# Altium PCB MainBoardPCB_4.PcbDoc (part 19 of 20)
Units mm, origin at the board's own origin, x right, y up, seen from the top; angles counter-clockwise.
Board outline 333.63 x 349.38 mm, 16 copper layers (L1, L2 (GND), L3 (Sign), L4 (GND), L5 (Sign), L6 (PWR/GND), L7(PWR/GND), L8 (Plane_GND), L9 (PWR/GND), L10 (PWR/GND), L11 (PWR/GND), L12 (Sign), L13 (GND), L14 (Sign), L15 (GND), L16), stack 2.502 mm thick; 2205 components, 1648 nets, 8314 pads, 3172 vias.
Unrouted connection lines stored in the file: 5141.
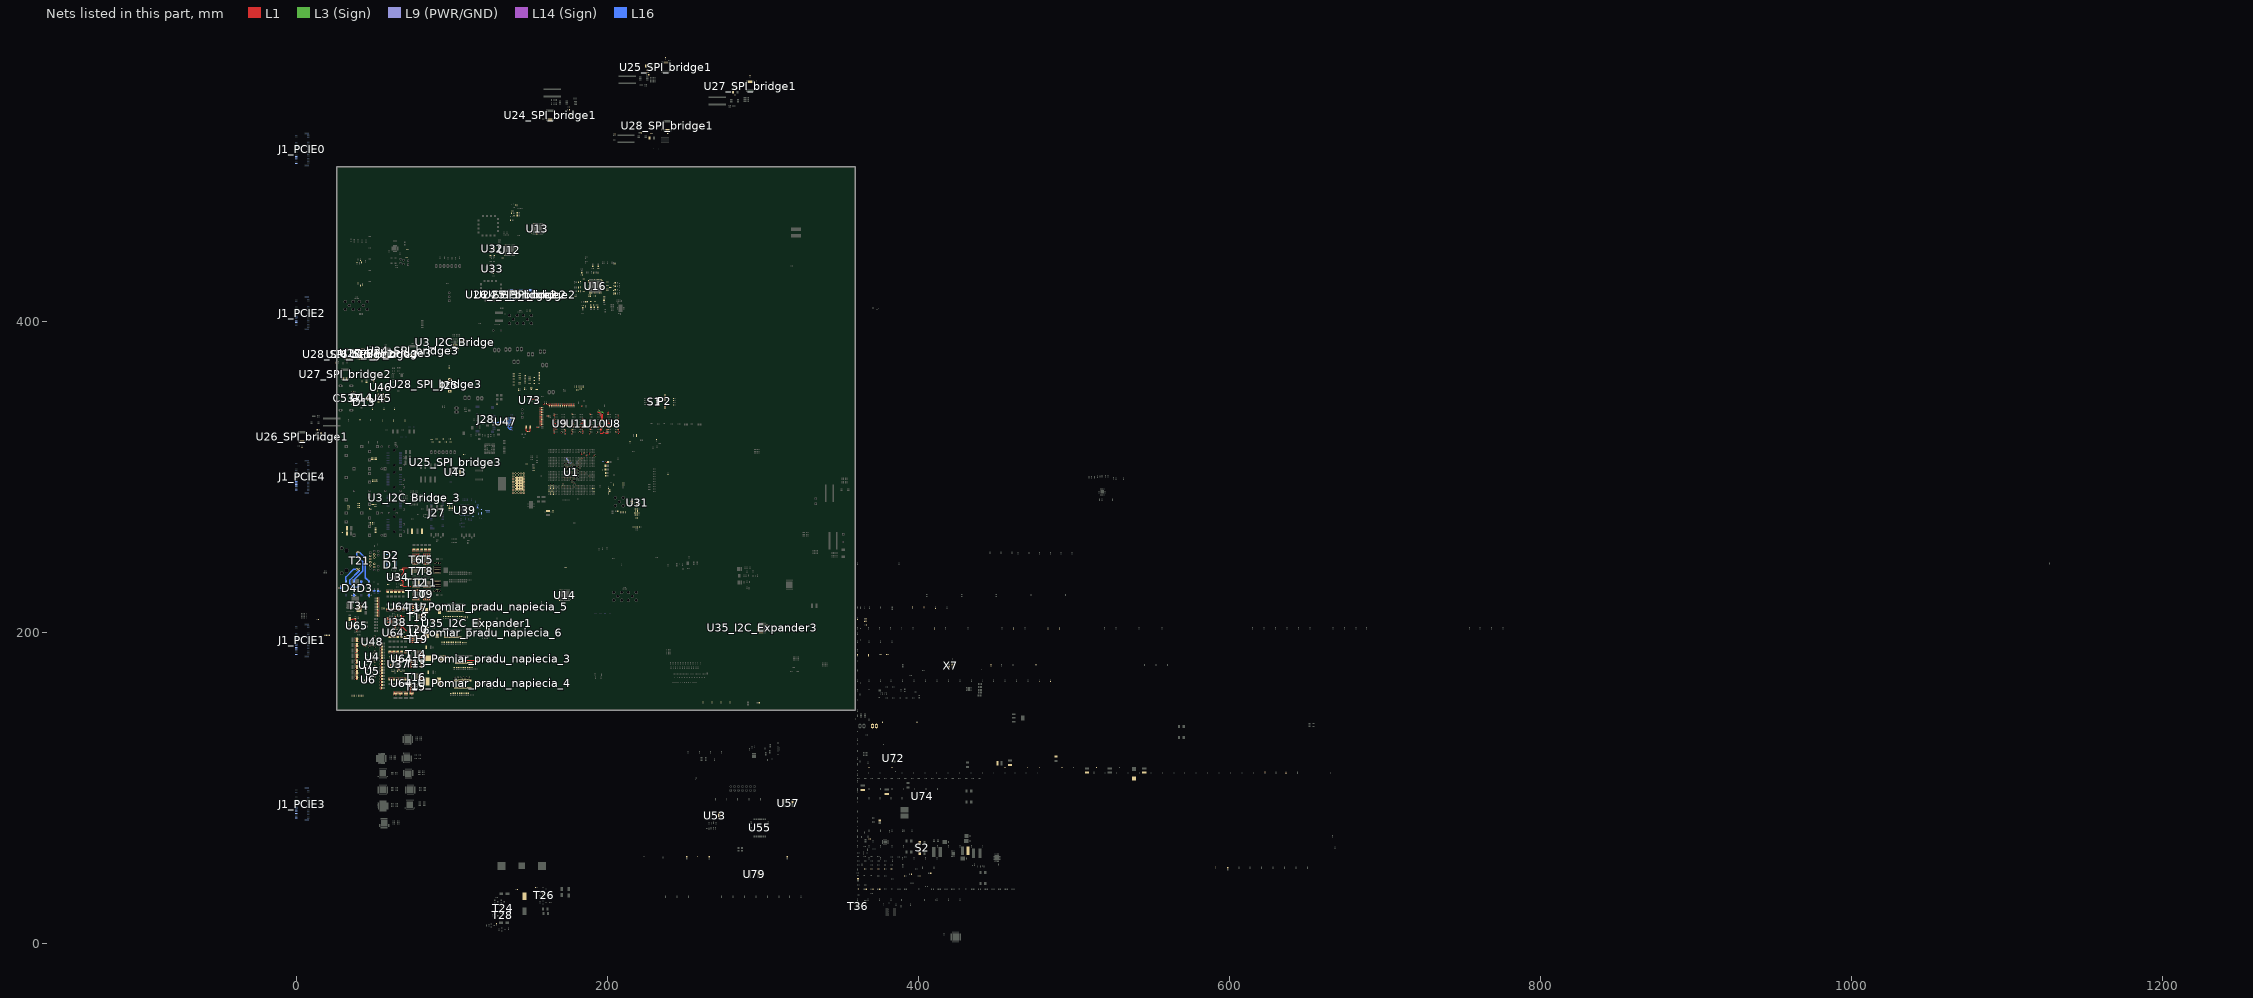
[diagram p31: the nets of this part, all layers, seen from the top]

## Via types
v1: diameter 0.5, hole 0.2, L1 to L16, tented both sides, 1153 vias
v2: diameter 0.5/0.35/0.35/0.35/0.35/0.35/0.35/0.35/0.35/0.35/0.35/0.35/0.35/0.35/0.35/0.5 (per signal layer), hole 0.2, L1 to L16, tented both sides, 548 vias
v3: diameter 0.5, hole 0.2, L1 to L16, 522 vias
v4: diameter 0.5/0.35/0.35/0.35/0.35/0.35/0.35/0.35/0.35/0.35/0.35/0.35/0.35/0.35/0.35/0.5 (per signal layer), hole 0.15, L1 to L16, tented both sides, 266 vias
v5: diameter 0.8, hole 0.4, L1 to L16, tented both sides, 164 vias
v6: diameter 0.35/0/0.35 (per signal layer), hole 0.127, L1 to L3 (Sign), tented both sides, 132 vias
v7: diameter 2.54, hole 1.02, L1 to L16, 125 vias
v8: diameter 1.4, hole 0.5, L1 to L16, tented both sides, 80 vias
v9: diameter 0.35, hole 0.127, L1 to L2 (GND), tented both sides, 36 vias
v10: diameter 0.4, hole 0.2, L1 to L16, 16 vias
v11: diameter 0.25, hole 0.2, L1 to L16, 16 vias
v12: diameter 5, hole 3, L1 to L16, 15 vias
v13: diameter 0.3, hole 0.2, L1 to L16, 15 vias
v14: diameter 0.45, hole 0.15, L1 to L16, 12 vias
v15: diameter 0.5/0.35/0.35/0.35/0.35/0.35/0.35/0.35/0.35/0.35/0.35/0.35/0.35/0.35/0.35/0.45 (per signal layer), hole 0.15, L1 to L16, tented both sides, 10 vias
v16: diameter 0.2/0/0.2 (per signal layer), hole 0.1, L1 to L3 (Sign), tented both sides, 9 vias
v17: diameter 0.4, hole 0.1, L1 to L16, 7 vias
v18: diameter 0.5, hole 0.2, L3 (Sign) to L6 (PWR/GND), tented both sides, 6 vias
v19: diameter 1.65, hole 1.65, L1 to L16, 6 vias
v20: diameter 1.15, hole 1.15, L1 to L16, 6 vias
v21: diameter 0.35/0/0.35 (per signal layer), hole 0.127, L14 (Sign) to L16, tented both sides, 5 vias
v22: diameter 0.2, hole 0.1, L1 to L16, 4 vias
v23: diameter 0.4, hole 0.2, L1 to L16, tented both sides, 2 vias
v24: diameter 0.4, hole 0.15, L1 to L16, 2 vias
v25: diameter 0.508, hole 0.127, L1 to L2 (GND), 2 vias
v26: diameter 0.508, hole 0.127, L2 (GND) to L3 (Sign), 2 vias
v27: diameter 0.5/0.35/0.35/0.35/0.35/0.35/0.35/0.35/0.35/0.35/0.35/0.35/0.35/0.35/0.35/0.5 (per signal layer), hole 0.15, L1 to L16, 2 vias
v28: diameter 0.35, hole 0.127, L3 (Sign) to L6 (PWR/GND), tented both sides, 2 vias
v29: diameter 5.5, hole 3.5, L1 to L16, 1 vias
v30: diameter 0.5/0.35/0.35/0.35/0.35/0.35/0.35/0.35/0.35/0.35/0.35/0.35/0.35/0.35/0.35/0.5 (per signal layer), hole 0.2, L1 to L16, 1 vias
v31: diameter 0.35/0.35/0.35 (per signal layer), hole 0.127, L1 to L3 (Sign), tented both sides, 1 vias
v32: diameter 0.45/0/0.45 (per signal layer), hole 0.15, L1 to L3 (Sign), tented both sides, 1 vias
v33: diameter 0.45/0/0.45 (per signal layer), hole 0.2, L14 (Sign) to L16, tented both sides, 1 vias
v34: diameter 0.35, hole 0.127, L2 (GND) to L3 (Sign), 1 vias
v35: diameter 0.35, hole 0.127, L1 to L2 (GND), 1 vias

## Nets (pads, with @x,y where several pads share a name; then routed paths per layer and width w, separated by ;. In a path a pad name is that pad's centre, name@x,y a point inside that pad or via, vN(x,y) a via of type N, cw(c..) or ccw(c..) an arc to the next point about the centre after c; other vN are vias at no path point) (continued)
PWR_OUT_20V: C347.2 C348.2 C352.2 C353.2 C371.2 C372.2 C373.2 C374.2 C375.2 C376.2 C391.1 C392.2 C396.2 C397.1 C400.2 C401.2 C402.2 C403.2 C404.2 C405.2 C432.1 C433.2 C437.2 C438.1 C441.2 C442.2 C443.2 C444.2 C445.2 C446.2 C766.1 C767.1 C768.1 C769.1 C770.2 C771.2 C772.2 C773.2 C774.2 C775.2 C776.2 C777.2 C778.2 C779.2 C780.2 C781.2 R266.2 R268.1 R285.1 R303.1 R612.2 R614.2 R621.2 R622.2 R628.2 R686.2 T5.5 T5.6 T5.7 T5.8 T6.5 T6.6 T6.7 T6.8 T9.5 T9.6 T9.7 T9.8 T10.5 T10.6 T10.7 T10.8 T13.5 T13.6 T13.7 T13.8 T15.5 T15.6 T15.7 T15.8 T17.5 T17.6 T17.7 T17.8 T19.5 T19.6 T19.7 T19.8 U48.1 U48.8 | length 169.6
  L1 w0.5: C780.2@52.066,210.593 v1(53.153,210.593) ; C780.2@52.066,211.317 v1(53.153,211.317) ; C779.2@52.066,212.488 v1(53.153,212.488) ; C779.2@52.066,213.212 v1(53.153,213.212) ; C778.2@52.066,214.297 v1(53.153,214.297) ; C778.2@52.066,215.021 v1(53.153,215.021) ; C777.2@52.067,216.111 v1(53.154,216.111) ; C777.2@52.066,216.835 v1(53.153,216.835) ; C776.2@52.066,217.856 v1(53.153,217.856) ; C776.2@52.066,218.58 v1(53.153,218.58) ; C775.2@52.066,219.678 v1(53.153,219.678) ; C775.2@52.066,220.402 v1(53.153,220.402) ; C774.2@52.066,221.492 v1(53.153,221.492) ; C774.2@52.066,222.216 v1(53.153,222.216) ; C392.2@58.13,226.088 v1(58.13,227.175) ; v1(58.214,213.896) C397.1@58.214,214.983 ; C392.2@58.776,226.088 v1(58.776,227.175) ; v1(58.852,213.896) C397.1@58.852,214.983 ; C392.2@59.413,226.088 v1(59.413,227.175) ; v1(59.497,213.896) C397.1@59.497,214.983 ; C433.2@59.63,169.623 v1(59.63,170.71) ; C353.2@59.645,197.03 v1(59.645,198.117) ; v1(59.653,186.744) C438.1@59.653,187.831 ; C433.2@60.276,169.623 v1(60.276,170.71) ; v1(60.29,186.744) C438.1@60.29,187.831 ; C353.2@60.29,197.03 v1(60.29,198.117) ; C391.1@60.612,226.088 v1(60.612,227.175) ; v1(60.696,213.896) C396.2@60.696,214.983 ; C433.2@60.913,169.623 v1(60.913,170.71) ; C353.2@60.928,197.03 v1(60.928,198.117) ; v1(60.935,186.744) C438.1@60.935,187.831 ; C391.1@61.258,226.088 v1(61.258,227.175) ; v1(61.334,213.896) C396.2@61.334,214.983 ; C391.1@61.895,226.088 v1(61.895,227.175) ; v1(61.979,213.896) C396.2@61.979,214.983 ; C432.1@62.112,169.623 v1(62.112,170.71) ; C352.2@62.127,197.03 v1(62.127,198.117) ; v1(62.135,186.744) C437.2@62.135,187.831 ; C769.1@62.575,160.649 v1(62.575,161.736) ; C432.1@62.758,169.623 v1(62.758,170.71) ; v1(62.772,186.744) C437.2@62.772,187.831 ; C352.2@62.772,197.03 v1(62.772,198.117) ; C405.2@63.094,226.087 v1(63.094,227.174) ; v1(63.124,159.562) C769.1@63.124,160.649 ; v1(63.179,213.896) C402.2@63.179,214.983 ; C432.1@63.395,169.623 v1(63.395,170.71) ; C352.2@63.41,197.03 v1(63.41,198.117) ; v1(63.417,186.744) C437.2@63.417,187.831 ; C769.1@63.68,160.649 v1(63.68,161.736) ; C405.2@63.74,226.087 v1(63.74,227.174) ; v1(63.816,213.896) C402.2@63.816,214.983 ; v1(64.229,159.562) C769.1@64.229,160.649 ; C405.2@64.377,226.087 v1(64.377,227.174) ; v1(64.461,213.896) C402.2@64.461,214.983 ; C446.2@64.594,169.623 v1(64.594,170.71) ; C374.2@64.609,197.03 v1(64.609,198.117) ; v1(64.617,186.744) C443.2@64.617,187.831 ; C769.1@64.777,160.649 v1(64.777,161.736) ; C446.2@65.24,169.623 v1(65.24,170.71) ; v1(65.254,186.744) C443.2@65.254,187.831 ; C374.2@65.254,197.03 v1(65.254,198.117) ; C404.2@65.576,226.087 v1(65.576,227.174) ; v1(65.661,213.896) C401.2@65.661,214.983 ; C446.2@65.877,169.623 v1(65.877,170.71) ; C374.2@65.892,197.03 v1(65.892,198.117) ; v1(65.899,186.744) C443.2@65.899,187.831 ; C768.1@65.979,160.649 v1(65.979,161.736) ; C404.2@66.222,226.087 v1(66.222,227.174) ; v1(66.298,213.896) C401.2@66.298,214.983 ; v1(66.527,159.563) C768.1@66.527,160.649 ; C404.2@66.859,226.087 v1(66.859,227.174) ; v1(66.943,213.896) C401.2@66.943,214.983 ; C445.2@67.076,169.623 v1(67.076,170.71) ; C768.1@67.084,160.649 v1(67.084,161.736) ; C371.2@67.091,197.03 v1(67.091,198.117) ; v1(67.099,186.744) C442.2@67.099,187.831 ; v1(67.632,159.563) C768.1@67.632,160.649 ; C445.2@67.722,169.623 v1(67.722,170.71) ; v1(67.736,186.744) C442.2@67.736,187.831 ; C371.2@67.736,197.03 v1(67.736,198.117) ; C403.2@68.058,226.057 v1(68.058,227.144) ; v1(68.143,213.866) C400.2@68.143,214.953 ; C768.1@68.181,160.649 v1(68.181,161.736) ; C445.2@68.359,169.623 v1(68.359,170.71) ; C371.2@68.374,197.03 v1(68.374,198.117) ; v1(68.382,186.744) C442.2@68.382,187.831 ; C403.2@68.704,226.057 v1(68.704,227.144) ; v1(68.78,213.866) C400.2@68.78,214.953 ; C403.2@69.341,226.057 v1(69.341,227.144) ; C767.1@69.419,160.65 v1(69.419,161.737) ; v1(69.425,213.866) C400.2@69.425,214.953 ; C444.2@69.558,169.592 v1(69.558,170.679) ; C376.2@69.573,196.999 v1(69.573,198.086) ; v1(69.581,186.713) C441.2@69.581,187.8 ; v1(69.967,159.563) C767.1@69.967,160.65 ; C444.2@70.204,169.592 v1(70.204,170.679) ; v1(70.218,186.713) C441.2@70.218,187.8 ; C376.2@70.218,196.999 v1(70.218,198.086) ; C767.1@70.524,160.65 v1(70.524,161.737) ; C444.2@70.841,169.592 v1(70.841,170.679) ; C376.2@70.856,196.999 v1(70.856,198.086) ; v1(70.864,186.713) C441.2@70.864,187.8 ; v1(71.072,159.563) C767.1@71.072,160.65 ; C767.1@71.621,160.65 v1(71.621,161.737) ; v1(72.877,163.201) T15.8@73.964,163.201 ; v1(72.877,164.471) T15.7@73.964,164.471 ; v1(72.877,165.741) T15.6@73.964,165.741 ; v1(72.877,167.011) T15.5@73.964,167.011 ; C766.1@72.887,160.649 v1(72.887,161.736) ; v1(73.13,178.003) T13.8@74.217,178.003 ; v1(73.13,179.273) T13.7@74.217,179.273 ; v1(73.13,180.543) T13.6@74.217,180.543 ; v1(73.13,181.813) T13.5@74.217,181.813 ; v1(73.435,159.562) C766.1@73.435,160.649 ; C766.1@73.992,160.649 v1(73.992,161.736) ; v1(74.017,193.746) T19.8@75.104,193.746 ; v1(74.017,195.016) T19.7@75.104,195.016 ; v1(74.017,196.286) T19.6@75.104,196.286 ; v1(74.017,197.556) T19.5@75.104,197.556 ; v1(74.086,214.079) T17.8@75.173,214.079 ; v1(74.086,215.349) T17.7@75.173,215.349 ; v1(74.086,216.619) T17.6@75.173,216.619 ; v1(74.086,217.889) T17.5@75.173,217.889 ; v1(74.54,159.562) C766.1@74.54,160.649 ; v1(74.991,252.289) C348.2@74.991,253.376 ; T6.8@75.072,249.548 v1(75.072,250.635) ; v1(75.078,220.589) T10.5@75.078,221.676 ; C766.1@75.088,160.649 v1(75.088,161.736) ; v1(75.629,252.289) C348.2@75.629,253.376 ; v1(76.274,252.289) C348.2@76.274,253.376 ; T6.7@76.342,249.548 v1(76.342,250.635) ; v1(76.348,220.589) T10.6@76.348,221.676 ; v1(77.473,252.289) C347.2@77.473,253.376 ; T6.6@77.612,249.548 v1(77.612,250.635) ; v1(77.618,220.589) T10.7@77.618,221.676 ; v1(78.111,252.289) C347.2@78.111,253.376 ; v1(78.756,252.289) C347.2@78.756,253.376 ; T6.5@78.882,249.548 v1(78.882,250.635) ; v1(78.888,220.589) T10.8@78.888,221.676 ; v1(79.955,252.288) C372.2@79.955,253.375 ; v1(80.593,252.288) C372.2@80.593,253.376 ; v1(81.238,252.288) C372.2@81.238,253.375 ; v1(82.072,220.589) T9.5@82.072,221.676 ; T5.8@82.072,249.548 v1(82.072,250.635) ; v1(82.437,252.288) C375.2@82.437,253.375 ; v1(83.075,252.288) C375.2@83.075,253.376 ; v1(83.342,220.589) T9.6@83.342,221.676 ; T5.7@83.342,249.548 v1(83.342,250.635) ; v1(83.72,252.288) C375.2@83.72,253.375 ; v1(84.612,220.589) T9.7@84.612,221.676 ; T5.6@84.612,249.548 v1(84.612,250.635) ; v1(84.919,252.258) C373.2@84.919,253.345 ; v1(85.557,252.258) C373.2@85.557,253.345 ; v1(85.882,220.589) T9.8@85.882,221.676 ; T5.5@85.882,249.548 v1(85.882,250.635) ; v1(86.202,252.258) C373.2@86.202,253.345
  other v1: 74.782,163.22 76.034,163.22 77.285,163.22 74.782,164.471 76.034,164.471 77.285,164.471 74.782,165.723 76.034,165.723 77.285,165.723 74.782,166.975 76.034,166.975 77.285,166.975 75.035,178.022 76.287,178.022 77.539,178.022 75.035,179.273 76.287,179.273 77.539,179.273 75.035,180.525 76.287,180.525 77.539,180.525 75.035,181.777 76.287,181.777 77.539,181.777 75.922,193.764 77.173,193.764 78.425,193.764 75.922,195.016 77.173,195.016 78.425,195.016 75.922,196.267 77.173,196.267 78.425,196.267 75.922,197.519 77.173,197.519 78.425,197.519 75.991,214.097 77.243,214.097 78.495,214.097 75.991,215.349 77.243,215.349 78.495,215.349 75.991,216.6 77.243,216.6 78.495,216.6 75.991,217.852 77.243,217.852 78.495,217.852 75.114,222.494 76.366,222.494 77.618,222.494 78.869,222.494 82.108,222.494 83.36,222.494 84.612,222.494 85.863,222.494 75.114,223.745 76.366,223.745 77.618,223.745 78.869,223.745 82.108,223.745 83.36,223.745 84.612,223.745 85.863,223.745 75.114,224.997 76.366,224.997 77.618,224.997 78.869,224.997 82.108,224.997 83.36,224.997 84.612,224.997 85.863,224.997 75.09,246.226 76.342,246.226 77.593,246.226 78.845,246.226 82.09,246.226 83.342,246.226 84.593,246.226 85.845,246.226 75.09,247.478 76.342,247.478 77.593,247.478 78.845,247.478 82.09,247.478 83.342,247.478 84.593,247.478 85.845,247.478 75.09,248.73 76.342,248.73 77.593,248.73 78.845,248.73 82.09,248.73 83.342,248.73 84.593,248.73 85.845,248.73
  other v5: 50.447,190.32 49.788,191.057 49.2,191.821 50.448,191.822 49.2,196.145 50.448,196.145 49.788,196.91 50.447,197.647
  other v10: 49.027,193.583 49.027,194.383
PWR_Switch1_En: U6.A2 U35_I2C_Expander1.3
PWR_Switch1_Flag: U35_I2C_Expander1.2
PWR_Switch2_En: U7.A2 U35_I2C_Expander1.22
PWR_Switch2_Flag: U35_I2C_Expander1.18
PWR_SwitchR1_Flag: R29.1 U6.A3
PWR_SwitchR2_Flag: R30.1 U7.A3
RAM_DDR4_VTT: C722.2 C723.2 R31.2 R32.2 R33.2 R34.2 R35.2 R36.2 R37.2 R38.2 R39.2 R40.2 R41.2 R42.2 R43.2 R44.2 R45.2 R46.2 R47.2 R48.2 R49.2 R50.2 R51.2 R53.2 R55.2 R57.2 R59.2 R689.1 U73.8 | length 34.8
  L1 w0.25: v1(156.593,333.611) R46.2@157.837,333.611 ; v1(156.593,334.7) R59.2@157.837,334.7 ; v1(156.593,335.789) R51.2@157.837,335.789 ; v1(156.593,336.878) R57.2@157.837,336.878 ; v1(156.593,337.967) R37.2@157.837,337.967 ; v1(156.593,339.056) R34.2@157.837,339.055 ; v1(156.593,340.144) R33.2@157.837,340.144 ; v1(156.593,341.233) R41.2@157.837,341.233 ; v1(156.593,342.322) R48.2@157.837,342.322 ; v1(156.593,343.411) R45.2@157.837,343.411 ; v1(156.593,344.5) R53.2@157.837,344.5 ; R38.2@162.769,345.7 v1(162.769,346.944) ; R44.2@163.977,345.7 v1(163.977,346.944) ; R55.2@165.186,345.7 v1(165.186,346.944) ; R40.2@166.395,345.7 v1(166.395,346.944) ; R36.2@167.603,345.7 v1(167.603,346.944) ; R49.2@168.812,345.7 v1(168.812,346.944) ; R32.2@170.02,345.7 v1(170.02,346.944) ; R39.2@171.229,345.7 v1(171.229,346.944) ; R42.2@172.438,345.7 v1(172.438,346.944) ; R35.2@173.646,345.7 v1(173.646,346.944) ; R31.2@174.855,345.7 v1(174.855,346.944) ; R50.2@176.063,345.7 v1(176.063,346.944) ; R47.2@177.272,345.7 v1(177.272,346.944) ; R43.2@178.481,345.7 v1(178.481,346.944)
  L1 w0.3: U73.8@151.644,349.985 v1(152.387,349.985) ; C722.2@153.683,349.532 v1(153.683,350.275) ; C723.2@154.673,349.532 v1(154.673,350.275) ; v1(158.909,347.162) 159.652,347.162 ; R689.1@160.795,347.112 v1(161.538,347.112)
RAM_Vcc1V2: C36.2 C220.1 C222.1 C223.2 C224.2 C225.2 C226.2 C227.2 C228.2 C229.2 C230.2 C231.2 C232.2 C233.2 C234.2 C235.2 C236.2 C237.2 C238.2 C239.2 C240.2 C241.2 C242.2 C244.1 C246.1 C247.2 C248.2 C249.2 C250.2 C251.2 C252.2 C253.2 C254.2 C255.2 C256.2 C257.2 C258.2 C259.2 C260.2 C261.2 C262.2 C263.2 C264.2 C265.2 C266.2 C741.2 C760.1 C761.2 R58.2 R165.2 R166.2 R169.2 R171.2 R297.2 R448_U_Pomiar_pradu_napiecia_4.2 R695.1 U1.A6 U1.B8 U1.C6 U1.D8 U1.E6 U1.G6 U1.J6 U1.L6 U1.M25 U1.N6 U1.R6 U1.T18 U1.T20 U1.T21 U1.U6 U8.A1 U8.A6 U8.B3 U8.B6 U8.C1 U8.D1 U8.D6 U8.F2 U8.F5 U8.G1 U8.G4 U8.G6 U8.J1 U8.J2 U8.J5 U8.J6 U8.L1 U8.L6 U8.R1 U8.T6 U9.A1 U9.A6 U9.B3 U9.B6 U9.C1 U9.D1 U9.D6 U9.F2 U9.F5 U9.G1 U9.G4 U9.G6 U9.J1 U9.J2 U9.J5 U9.J6 U9.L1 U9.L6 U9.R1 U9.T6 U10.A1 U10.A6 U10.B3 U10.B6 U10.C1 U10.D1 U10.D6 U10.F2 U10.F5 U10.G1 U10.G4 U10.G6 U10.J1 U10.J2 U10.J5 U10.J6 U10.L1 U10.L6 U10.R1 U10.T6 U11.A1 U11.A6 U11.B3 U11.B6 U11.C1 U11.D1 U11.D6 U11.F2 U11.F5 U11.G1 U11.G4 U11.G6 U11.J1 U11.J2 U11.J5 U11.J6 U11.L1 U11.L6 U11.R1 U11.T6 U64_U_Pomiar_pradu_napiecia_4.8 U64_U_Pomiar_pradu_napiecia_4.9 | length 89
  L1 w0.2: v4(189.4,334.057) v4@189.4,334.064 ; v1(198.412,328.613) 198.964,328.06 U8.A6@200.457,328.06 ; v1(199.479,328.887) 200.43,328.887 U8.B6@200.457,328.86 ; v1(199.657,330.225) 199.892,330.46 U8.D6@200.457,330.46 ; U8.G4@202.057,332.86 202.215,332.702 v4(202.757,332.702) ; U8.J2@206.057,334.46 206.18,334.337 206.734,334.337 U8.J1@206.857,334.46 v4(207.261,334.864) ; U8.A1@206.857,328.06 v4(207.785,328.06) ; U8.C1@206.857,329.66 v4(207.785,329.66) ; U8.D1@206.857,330.46 v4(207.785,330.46) ; U8.G1@206.857,332.86 v4(207.428,332.86) ; U8.L1@206.857,336.06 v4(207.261,336.464) ; U8.R1@206.857,339.26 v4(207.261,339.664)
  L1 w0.25: v1(154.724,331.965) C36.2@155.566,331.965 ; v1(161.216,339.242) R58.2@162.46,339.242 ; v4(165.672,328.464) U9.A6@166.076,328.06 ; v4(165.672,329.264) U9.B6@166.076,328.86 ; v4(165.672,330.064) 166.076,329.66 ; v4(165.672,330.864) U9.D6@166.076,330.46 ; v4(165.672,331.664) 166.076,331.26 ; v4(165.672,333.264) U9.G6@166.076,332.86 ; v4(165.672,334.864) U9.J6@166.076,334.46 U9.J5@166.876,334.46 ; v4(165.672,336.464) U9.L6@166.076,336.06 ; v4(165.672,337.264) 166.076,336.86 ; v4(165.672,339.664) 166.076,339.26 ; v4(165.672,340.464) U9.T6@166.076,340.06 ; v4(166.472,330.864) 166.876,330.46 ; v4(166.472,331.664) 166.876,331.26 ; v4(166.472,332.457) 166.876,332.86 ; U9.F5@166.876,332.06 v4(167.279,332.464) ; v4(167.272,333.264) U9.G4@167.676,332.86 ; v4(170.472,328.457) U9.B3@170.876,328.86 ; v4(171.272,334.057) U9.J2@171.676,334.46 ; U9.F2@171.676,332.06 172.876,333.261 v4(172.923,333.261) ; U9.A1@172.476,328.06 v4(172.879,327.657) ; U9.C1@172.476,329.66 v4(172.879,329.257) ; U9.D1@172.476,330.46 v4(172.879,330.057) ; U9.J1@172.476,334.46 v4(172.879,334.864) ; v4(176.95,336.055) U11.L6@177.521,336.055 ; v4(177.133,327.657) U11.A6@177.536,328.06 ; v4(177.133,328.457) U11.B6@177.536,328.86 ; v4(177.133,330.057) U11.D6@177.536,330.46 ; v4(177.133,332.457) U11.G6@177.536,332.86 ; v4(177.133,334.057) U11.J6@177.536,334.46 ; v4(177.133,340.464) U11.T6@177.536,340.06 ; v4(177.933,331.657) U11.F5@178.336,332.06 ; v4(177.933,334.057) U11.J5@178.336,334.46 ; U11.G4@179.136,332.86 v4(179.54,332.457) ; v4(181.933,328.457) U11.B3@182.336,328.86 ; v4(182.733,331.657) U11.F2@183.136,332.06 ; v4(182.733,334.057) U11.J2@183.136,334.46 ; 183.451,345.211 v4(183.855,345.615) ; U11.A1@183.936,328.06 v4(184.507,328.06) ; U11.C1@183.936,329.66 v4(184.507,329.66) ; U11.D1@183.936,330.46 v4(184.507,330.46) ; U11.G1@183.936,332.86 v4(184.507,332.86) ; U11.J1@183.936,334.46 v4(184.34,334.864) ; U11.L1@183.936,336.06 v4(184.34,335.657) ; v4(188.593,327.657) U10.A6@188.997,328.06 ; v4(188.593,328.457) U10.B6@188.997,328.86 ; v4(188.593,330.864) U10.D6@188.997,330.46 ; v4(188.593,336.464) U10.L6@188.997,336.06 ; v4(188.593,340.464) U10.T6@188.997,340.06 ; U10.J6@188.997,334.46 v4(189.4,334.057) ; v4(189.393,332.464) U10.F5@189.797,332.06 ; v4@189.4,334.064 U10.J5@189.797,334.46 ; U10.G4@190.597,332.86 v4(191,332.457) ; U10.F2@194.597,332.06 U10.G1@195.397,332.86 ; U8.B3@205.257,328.86 v4(205.661,328.457)
  L1 w0.254: v1(198.031,332.524) 200.121,332.524 U8.G6@200.457,332.86 U8.F5@201.257,332.06 ; 200.203,341.884 200.457,341.63 U8.T6@200.457,340.06 ; U8.L6@200.457,336.06 199.439,336.06 198.847,335.469 v1(198.847,334.75) 199.326,334.75 199.615,334.46 U8.J6@200.457,334.46 200.727,334.73 200.987,334.73 U8.J5@201.257,334.46 ; U8.F2@206.057,332.06 U8.G1@206.857,332.86
  L1 w0.3: v1(193.116,328.384) 193.32,328.384 U10.B3@193.797,328.86 ; U10.J2@194.597,334.46 195.008,334.049 U10.J1@195.397,334.46 195.644,334.213 v1(195.77,334.213) ; U10.A1@195.397,328.06 196.956,328.06 v1(198.022,329.127) ; U10.C1@195.397,329.66 195.643,329.66 196.494,330.512 v1(196.494,331.178) 196.114,331.178 U10.D1@195.397,330.46 ; U10.G1@195.397,332.86 195.441,332.816 195.791,332.816 196.812,331.795 v1(196.812,331.762) ; U10.L1@195.397,336.06 196.172,336.06 197.039,336.927 v6(197.039,340.639) ; U10.R1@195.397,339.26 195.988,339.852 v6(196.026,339.852)
  L9 (PWR/GND) w0.254: v2(173.397,312.539) 173.901,312.035 173.901,311.315 174.18,311.036 174.587,311.036 174.892,310.731 174.892,309.26 175.173,308.978 176.958,308.978
  L3 (Sign) w0.3: v1(194.323,342.976) 194.694,342.605 194.694,341.572 195.22,341.046 195.567,341.046 196.026,340.587 v6@196.026,339.831 ; v1(195.568,341.757) 196.748,341.757 197.104,341.401 197.039,341.336 v6(197.039,340.639)
  L16 w0.2: v1@199.452,328.887 v1(199.479,328.887)
  L16 w0.254: v1(198.847,334.75) v1@198.897,334.75
  L16 w0.3: v1@193.116,328.325 v1(193.116,328.384)
  other v2: 162.397,293.539 164.397,293.539 166.397,293.539 168.397,293.539 170.397,293.539 172.397,293.539 174.397,293.539 176.397,293.539 178.397,293.539 163.397,295.539 165.397,295.539 177.397,305.539 177.397,307.539 177.397,308.539
  other v5: 112.047,170.186 110.249,170.206 108.45,170.226 104.854,170.267 106.652,170.246 103.056,170.287 101.258,170.307 111.158,171.095 109.36,171.115 105.763,171.156 107.561,171.135 103.965,171.176 102.167,171.196
RAM_VrefA: C221.1 R166.1 R168.1 U8.M1 | length 0.6
  L1 w0.2: U8.M1@206.857,336.86 v4(207.261,337.264)
RAM_VrefB: C243.1 R169.1 R170.1 U10.M1 | length 7.8
  L1 w0.2: v6(193.786,341.617) 194.952,341.617 196.417,340.153 196.417,337.357 195.92,336.86 U10.M1@195.397,336.86
  L3 (Sign) w0.2: v6(193.786,341.617) 193.786,342.141
RAM_VrefC: C219.1 R165.1 R167.1 U9.M1
RAM_VrefD: C245.1 R171.1 R172.1 U11.M1 | length 0.6
  L1 w0.25: U11.M1@183.936,336.86 v4(184.34,337.264)
RefClk_Si53323_N: R253.1 R255.2 U31.7
RefClk_Si53323_P: C341.2 R252.1 R254.2 U31.6
RESET_N: R712.1 R713.2 U39.43
RESETB: U45.27 U74.4
RST_brigde: R757.1 U3_I2C_Bridge_3.24
SD_Card_CLK: J28.5 U47.C5 | length 6.8
  L16 w0.098: J28.5@127.237,335.032 130.228,335.032 130.6,335.404 U47.C5@133.927,335.404
SD_Card_en: R382.1 U47.C2
SetClk_Si53323_2: T36.1 U1.K12
  other v2: 171.397,299.539
SFP0_ABS: R65.1
SFP0_LOS: R66.1 U35_I2C_Expander3.28
SFP0_RS0: R72.1 R74.2
SFP0_RS1: R71.1 R73.2
SFP0_Rx_N: U1.D5
SFP0_Rx_P: U1.D6
SFP0_Tx_N: U1.D1
SFP0_Tx_P: U1.D2
SFP0_TxDis: R68.1 U35_I2C_Expander3.27
SFP0_TxF: R67.1 U35_I2C_Expander3.26
SFP0_VccR: C37.2 C38.1 L1.2
SFP0_VccT: C39.2 C40.1 L2.2
SFP1_ABS: R135.1
SFP1_GND: R143.1 R144.1
SFP1_LOS: R136.1 U35_I2C_Expander3.4
SFP1_RS0: R142.1 R144.2
SFP1_RS1: R141.1 R143.2
SFP1_Rx_N: U1.C7
SFP1_Rx_P: U1.C8
SFP1_Tx_N: U1.C3
SFP1_Tx_P: U1.C4
SFP1_TxDis: R138.1 U35_I2C_Expander3.1
SFP1_TxF: R137.1 U35_I2C_Expander3.24
SFP2_ABS: R145.1
SFP2_GND: R153.1 R154.1
SFP2_LOS: R146.1 U35_I2C_Expander3.3
SFP2_RS0: R152.1 R154.2
SFP2_RS1: R151.1 R153.2
SFP2_Rx_N: U1.B5
SFP2_Rx_P: U1.B6
SFP2_Tx_N: U1.B1
SFP2_Tx_P: U1.B2
SFP2_TxDis: R148.1 U35_I2C_Expander3.17
SFP2_TxF: R147.1 U35_I2C_Expander3.19
SFP3_ABS: R155.1
SFP3_GND: R163.1 R164.1
SFP3_LOS: R156.1 U35_I2C_Expander3.21
SFP3_RS0: R162.1 R164.2
SFP3_RS1: R161.1 R163.2
SFP3_Rx_N: U1.A7
SFP3_Rx_P: U1.A8
SFP3_Tx_N: U1.A3
SFP3_Tx_P: U1.A4
SFP3_TxDis: R158.1 U35_I2C_Expander3.18
SFP3_TxF: R157.1 U35_I2C_Expander3.2
SFP_IO_nReset: R756.1 U35_I2C_Expander3.14
SGMI_C_Rx_N: C484.1
SGMI_C_Rx_P: C483.1
SGMI_C_Tx_N: C482.1
SGMI_C_Tx_P: C479.1
SGMI_CLK_Out_N: R320.1 R321.1 R326.2 U39.34
SGMI_CLK_Out_P: R319.1 R321.2 R325.2 U39.33
SGMI_Rx_N: C484.2 U39.28
SGMI_Rx_P: C483.2 U39.27
SGMI_Tx_N: C482.2 R323.1 R328.2 U39.36
SGMI_Tx_P: C479.2 R322.1 R327.2 U39.35
Si53323_1_Q1_N: C330.1 R249.1 U31.9
Si53323_1_Q1_P: C325.1 R246.2 U31.10
Si53323_1_Q2_LVDS_N: C725.2 R386.2 R387.2
Si53323_1_Q2_LVDS_P: C724.2
Si53323_1_Q2_N: R301.1 R385.2 U31.12
Si53323_1_Q2_P: R291.1 R384.2 U31.11
Si53323_2_CLK1_N: C330.2 R245.2 R248.2 R251.2 U32.4
Si53323_2_CLK1_P: C325.2 R245.1 R247.2 R250.2 U32.3
Si53323_2_Q1_N: C54.2 R537.2 U32.10
Si53323_2_Q1_P: C53.2 R536.1 U32.9
Si53323_2_Q2_LVDS_N: C727.2 R486.2 R487.2
Si53323_2_Q2_LVDS_P: C726.2
Si53323_2_Q2_N: R483.1 R485.2 U32.12
Si53323_2_Q2_P: R482.1 R484.2 U32.11
SMCLK_PCIE0: J1_PCIE0.26 R559_I2C_Bridge.1 U3_I2C_Bridge.2
SMCLK_PCIE1: J1_PCIE1.26 R227_I2C_Bridge.1 U3_I2C_Bridge.4
SMCLK_PCIE2: J1_PCIE2.26 R225_I2C_Bridge.1 U3_I2C_Bridge.6
SMCLK_PCIE3: J1_PCIE3.26 R223_I2C_Bridge.1 U3_I2C_Bridge.8
SMCLK_PCIE4: J1_PCIE4.26 R9_I2C_Bridge.1 U3_I2C_Bridge.11
SMDAT_PCIE0: J1_PCIE0.28 R560_I2C_Bridge.1 U3_I2C_Bridge.1
SMDAT_PCIE1: J1_PCIE1.28 R558_I2C_Bridge.1 U3_I2C_Bridge.3
SMDAT_PCIE2: J1_PCIE2.28 R226_I2C_Bridge.1 U3_I2C_Bridge.5
SMDAT_PCIE3: J1_PCIE3.28 R224_I2C_Bridge.1 U3_I2C_Bridge.7
SMDAT_PCIE4: J1_PCIE4.28 R10_I2C_Bridge.1 U3_I2C_Bridge.10
SPI1_CLK: 
SPI1_CLK: J25.1 R803.1 U15.14 U24_SPI_bridge2.3 U24_SPI_bridge3.3 U25_SPI_bridge2.3 U25_SPI_bridge3.3 U26_SPI_bridge2.3 U26_SPI_bridge3.3 U27_SPI_bridge2.3 U27_SPI_bridge3.3 U28_SPI_bridge2.3 U28_SPI_bridge3.3
SPI1_CS: J25.4 R123.1 R124.1 R806.1 U15.11 U24_SPI_bridge2.6 U24_SPI_bridge3.6 U25_SPI_bridge2.6 U25_SPI_bridge3.6 U26_SPI_bridge2.6 U26_SPI_bridge3.6 U27_SPI_bridge2.6 U27_SPI_bridge3.6 U28_SPI_bridge2.6 U28_SPI_bridge3.6
SPI1_MISO: J25.3 R807.1 U15.13 U24_SPI_bridge2.4 U24_SPI_bridge3.4 U25_SPI_bridge2.4 U25_SPI_bridge3.4 U26_SPI_bridge2.4 U26_SPI_bridge3.4 U27_SPI_bridge2.4 U27_SPI_bridge3.4 U28_SPI_bridge2.4 U28_SPI_bridge3.4
SPI1_MISO: U12.51 U26_SPI_bridge2.13
SPI1_MOSI: 
SPI1_MOSI: J25.2 R808.1 U15.12 U24_SPI_bridge2.5 U24_SPI_bridge3.5 U25_SPI_bridge2.5 U25_SPI_bridge3.5 U26_SPI_bridge2.5 U26_SPI_bridge3.5 U27_SPI_bridge2.5 U27_SPI_bridge3.5 U28_SPI_bridge2.5 U28_SPI_bridge3.5
SPI1_MOSI: U12.52 U26_SPI_bridge2.12
SPI2_CLK: U13.50 U25_SPI_bridge2.14
SPI2_MISO: U13.51 U25_SPI_bridge2.13
SPI2_MOSI: U13.52 U25_SPI_bridge2.12
SPI3_CLK: U14.50 U24_SPI_bridge2.14
SPI3_MISO: U14.51 U24_SPI_bridge2.13
SPI3_MOSI: U14.52 U24_SPI_bridge2.12
SPI_05028_CS: 
SPI_05028_CS: R125.2 R127.1 R139.2 R240_SPI_bridge2.1 U16.24 U28_SPI_bridge2.11
SPI_05028_MISO: R1.1 R2.2 R133.1 U16.60
SPI_6952_1_CS: 
SPI_6952_1_CS: R236_SPI_bridge2.1 U12.1 U26_SPI_bridge2.11
SPI_6952_2_CS: R233_SPI_bridge2.1 U13.1 U25_SPI_bridge2.11
SPI_6952_2_CS: 
SPI_6952_3_CS: R231_SPI_bridge2.1 U14.1 U24_SPI_bridge2.11
SPI_CLK_PCIE0: J1_PCIE0.22 U24_SPI_bridge1.14
SPI_CLK_PCIE1: J1_PCIE1.22 U25_SPI_bridge1.14
SPI_CLK_PCIE2: J1_PCIE2.22 U26_SPI_bridge1.14
SPI_CLK_PCIE3: J1_PCIE3.22 U27_SPI_bridge1.14
SPI_CLK_PCIE4: J1_PCIE4.22 U28_SPI_bridge1.14
SPI_CNV: 
SPI_DAC_CS: R236_SPI_bridge3.1 U26_SPI_bridge3.11 U30.14
SPI_DAC_CS: 
SPI_FPGA_CLK: U1.AB15 U15.3
  other v2: 183.397,302.539
SPI_FPGA_CS: R365.2 U1.AG13 U15.6
  other v2: 188.397,300.539
SPI_FPGA_MISO: U1.AD15 U15.4
  other v2: 185.397,302.539
SPI_FPGA_MOSI: U1.AE15 U15.5
  other v2: 186.397,302.539
SPI_FPGA_nOE: U15.9
SPI_MISO_PCIE0: J1_PCIE0.18 U24_SPI_bridge1.13
SPI_MISO_PCIE1: J1_PCIE1.18 U25_SPI_bridge1.13
SPI_MISO_PCIE2: J1_PCIE2.18 U26_SPI_bridge1.13
SPI_MISO_PCIE3: J1_PCIE3.18 U27_SPI_bridge1.13
SPI_MISO_PCIE4: J1_PCIE4.18 U28_SPI_bridge1.13
SPI_MOSI_PCIE0: J1_PCIE0.20 U24_SPI_bridge1.12
SPI_MOSI_PCIE1: J1_PCIE1.20 U25_SPI_bridge1.12
SPI_MOSI_PCIE2: J1_PCIE2.20 U26_SPI_bridge1.12
SPI_MOSI_PCIE3: J1_PCIE3.20 U27_SPI_bridge1.12
SPI_MOSI_PCIE4: J1_PCIE4.20 U28_SPI_bridge1.12
SPI_nCS_1_PCIE0: J1_PCIE0.16 R231_SPI_bridge1.1 U24_SPI_bridge1.11
SPI_nCS_1_PCIE1: J1_PCIE1.16 R233_SPI_bridge1.1 U25_SPI_bridge1.11
SPI_nCS_1_PCIE2: J1_PCIE2.16 R236_SPI_bridge1.1 U26_SPI_bridge1.11
SPI_nCS_1_PCIE3: J1_PCIE3.16 R238_SPI_bridge1.1 U27_SPI_bridge1.11
SPI_nCS_1_PCIE4: J1_PCIE4.16 R240_SPI_bridge1.1 U28_SPI_bridge1.11
SPI_nCS_2_PCIE0: J1_PCIE0.14
SPI_nCS_2_PCIE1: J1_PCIE1.14
SPI_nCS_2_PCIE2: J1_PCIE2.14
SPI_nCS_2_PCIE3: J1_PCIE3.14
SPI_nCS_2_PCIE4: J1_PCIE4.14
SPI_PCIE_SWITCH: 
SPI_RESET: 
SS1_1: C639.2 U37.28 | length 1.7
  L1 w0.254: U37.28@65.675,181.817 65.675,182.903 C639.2@66.141,183.369
SS1_2: C647.2 U38.28 | length 1.6
  L1 w0.254: U38.28@63.953,208.714 C647.2@63.953,210.264
SS2_1: C640.2 U37.13 | length 1.6
  L1 w0.254: U37.13@65.675,177.317 65.675,176.584 66.161,176.097 C640.2@66.161,175.893
SS2_2: C648.2 U38.13 | length 1.5
  L1 w0.254: C648.2@63.741,202.763 63.741,203.154 63.953,203.366 U38.13@63.953,204.214
SUSCLK: J27.60
SW1: C346.2 L9.1 R610.2 R613.2 T5.1 T5.2 T5.3 T6.1 T6.2 T6.3 T7.5 T7.6 T7.7 T7.8 T8.5 T8.6 T8.7 T8.8 U34.24 | length 18.8
  L1 w0.254: U34.24@67.322,237.139 67.657,237.139 69.236,238.718 69.236,240.156 68.922,240.47 C346.2@68.336,240.47 ; R610.2@67.378,240.47 C346.2@68.336,240.47 ; 73.8,241.529 68.669,241.529 68.336,241.196 C346.2@68.336,240.47
  L1 w0.5: T6.1@75.072,243.723 v1(75.072,244.81) ; T6.2@76.342,243.723 v1(76.342,244.81) ; T6.3@77.612,243.723 v1(77.612,244.81) ; T5.1@82.072,243.723 v1(82.072,244.81) ; T5.2@83.342,243.723 v1(83.342,244.81) ; T5.3@84.612,243.723 v1(84.612,244.81)
  other v1: 88.711,238.28 89.517,238.28 90.322,238.28 91.128,238.28 91.934,238.28 92.74,238.28 75.09,238.992 76.342,238.992 77.593,238.992 78.845,238.992 82.09,238.992 83.342,238.992 84.593,238.992 85.845,238.992 88.711,239.086 89.517,239.086 90.322,239.086 91.128,239.086 91.934,239.086 92.74,239.086 88.711,239.892 89.517,239.892 90.322,239.892 91.128,239.892 91.934,239.892 92.74,239.892 75.09,240.244 76.342,240.244 77.593,240.244 78.845,240.244 82.09,240.244 83.342,240.244 84.593,240.244 85.845,240.244 88.711,240.697 89.517,240.697 90.322,240.697 91.128,240.697 91.934,240.697 92.74,240.697 75.09,241.496 76.342,241.496 77.593,241.496 78.845,241.496 82.09,241.496 83.342,241.496 84.593,241.496 85.845,241.496 88.711,241.503 89.517,241.503 90.322,241.503 91.128,241.503 91.934,241.503 92.74,241.503 88.711,242.309 89.517,242.309 90.322,242.309 91.128,242.309 91.934,242.309 92.74,242.309 89.212,244.228 90.018,244.228 90.823,244.228 91.629,244.228 92.435,244.228 88.788,244.811 89.594,244.811 90.4,244.811 91.206,244.811 92.011,244.811 92.817,244.811
SW1_1: C390.2 L11.1 R288.2 R619.2 T13.1 T13.2 T13.3 T14.5 T14.6 T14.7 T14.8 U37.24 | length 7.6
  L1 w0.5: T14.5@80.039,184.15 v1(81.126,184.15) ; T14.6@80.039,185.42 v1(81.126,185.42) ; T14.7@80.039,186.69 v1(81.126,186.69) ; T14.8@80.039,187.96 v1(81.126,187.96) ; T13.1@80.042,178.003 v1(81.129,178.003) ; T13.2@80.042,179.273 v1(81.129,179.273) ; T13.3@80.042,180.543 v1(81.129,180.543)
  other v1: 76.718,184.187 77.97,184.187 79.221,184.187 76.718,185.438 77.97,185.438 79.221,185.438 76.718,186.69 77.97,186.69 79.221,186.69 76.718,187.942 77.97,187.942 79.221,187.942
SW1_2: C431.2 L19.1 R306.2 R625.1 T17.1 T17.2 T17.3 T18.5 T18.6 T18.7 T18.8 U38.24 | length 11.2
  L1 w0.254: U38.24@65.953,208.214 67.293,208.214 67.758,208.68 C431.2@67.758,209.091 ; R625.1@67.001,210.879 67.377,210.879 67.781,210.475 C431.2@67.781,209.114 68.392,209.114 69.532,210.254 ; 77.166,206.68 77.677,207.192 77.677,207.477
  L1 w0.5: v1(79.911,214.079) T17.1@80.998,214.079 ; v1(79.911,215.349) T17.2@80.998,215.349 ; v1(79.911,216.619) T17.3@80.998,216.619
  other v1: 77.677,207.834 78.929,207.834 80.18,207.834 77.677,209.086 78.929,209.086 80.18,209.086 77.677,210.337 78.929,210.337 80.18,210.337 77.677,211.589 78.929,211.589 80.18,211.589
SW2: C350.2 L10.1 R611.2 R616.2 T9.1 T9.2 T9.3 T10.1 T10.2 T10.3 T11.5 T11.6 T11.7 T11.8 T12.5 T12.6 T12.7 T12.8 U34.17 | length 18.5
  L1 w0.254: R611.2@67.113,230.147 67.513,230.147 67.688,230.322 C350.2@68.072,230.322 ; U34.17@67.322,233.639 68.085,233.639 68.854,232.87 68.854,230.471 68.705,230.322 C350.2@68.072,230.322 ; C350.2@68.072,230.317 C350.2@68.072,230.322 ; 73.69,229.73 68.663,229.73 C350.2@68.072,230.322
  L1 w0.5: v1(76.348,226.414) T10.3@76.348,227.501 ; v1(77.618,226.414) T10.2@77.618,227.501 ; v1(78.888,226.414) T10.1@78.888,227.501 ; v1(83.342,226.414) T9.3@83.342,227.501 ; v1(84.612,226.414) T9.2@84.612,227.501 ; v1(85.882,226.414) T9.1@85.882,227.501
  other v1: 88.597,226.45 89.402,226.45 90.208,226.45 91.014,226.45 91.82,226.45 92.625,226.45 88.979,227.033 89.785,227.033 90.59,227.033 91.396,227.033 92.202,227.033 88.674,228.952 89.48,228.952 90.286,228.952 91.091,228.952 91.897,228.952 92.703,228.952 75.108,229.757 76.36,229.757 77.612,229.757 78.863,229.757 82.108,229.757 83.36,229.757 84.612,229.757 85.863,229.757 88.674,229.758 89.48,229.758 90.286,229.758 91.091,229.758 91.897,229.758 92.703,229.758 88.674,230.564 89.48,230.564 90.286,230.564 91.091,230.564 91.897,230.564 92.703,230.564 75.108,231.008 76.36,231.008 77.612,231.008 78.863,231.008 82.108,231.008 83.36,231.008 84.612,231.008 85.863,231.008 88.674,231.369 89.48,231.369 90.286,231.369 91.091,231.369 91.897,231.369 92.703,231.369 88.674,232.175 89.48,232.175 90.286,232.175 91.091,232.175 91.897,232.175 92.703,232.175 75.108,232.26 76.36,232.26 77.612,232.26 78.863,232.26 82.108,232.26 83.36,232.26 84.612,232.26 85.863,232.26 88.674,232.981 89.48,232.981 90.286,232.981 91.091,232.981 91.897,232.981 92.703,232.981
SW2_1: C394.2 L12.1 R298.2 R620.2 T15.1 T15.2 T15.3 T16.5 T16.6 T16.7 T16.8 U37.17 | length 7.6
  L1 w0.5: T15.1@79.789,163.201 v1(80.876,163.201) ; T15.2@79.789,164.471 v1(80.876,164.471) ; T15.3@79.789,165.741 v1(80.876,165.741) ; T16.5@79.835,169.38 v1(80.922,169.38) ; T16.6@79.835,170.65 v1(80.922,170.65) ; T16.7@79.835,171.92 v1(80.922,171.92) ; T16.8@79.835,173.19 v1(80.922,173.19)
  other v1: 76.514,169.417 77.766,169.417 79.017,169.417 76.514,170.668 77.766,170.668 79.017,170.668 76.514,171.92 77.766,171.92 79.017,171.92 76.514,173.172 77.766,173.172 79.017,173.172
SW2_2: C435.2 L20.1 R302.1 R316.2 T19.1 T19.2 T19.3 T20.5 T20.6 T20.7 T20.8 U38.17 | length 12.3
  L1 w0.254: U38.17@65.953,204.714 67.394,204.714 67.796,204.312 C435.2@67.796,203.864 ; R302.1@66.453,202.163 66.794,202.163 67.796,203.166 C435.2@67.796,203.864 ; 70.746,200.92 C435.2@67.796,203.864
  L1 w0.5: v1(79.842,193.746) T19.1@80.929,193.746 ; v1(79.842,195.016) T19.2@80.929,195.016 ; v1(79.842,196.286) T19.3@80.929,196.286
  other v1: 77.578,200.189 78.83,200.189 80.081,200.189 77.578,201.44 78.83,201.44 80.081,201.44 77.578,202.692 78.83,202.692 80.081,202.692 77.578,203.944 78.83,203.944 80.081,203.944
SYNC_PCIE0_N: J1_PCIE0.46
SYNC_PCIE0_P: J1_PCIE0.44
SYNC_PCIE1_N: J1_PCIE1.46
SYNC_PCIE1_P: J1_PCIE1.44
SYNC_PCIE2_N: J1_PCIE2.46
SYNC_PCIE2_P: J1_PCIE2.44
SYNC_PCIE3_N: J1_PCIE3.46
SYNC_PCIE3_P: J1_PCIE3.44
SYNC_PCIE4_N: J1_PCIE4.46
SYNC_PCIE4_P: J1_PCIE4.44
TD_A_N: D1.2 D1.7 T21.10 U39.2
TD_A_P: D1.1 D1.8 T21.11 U39.1
TD_B_N: D1.4 D1.5 T21.5 U39.5
TD_B_P: D1.3 D1.6 T21.4 U39.4
TD_C_N: D2.2 D2.7 T21.2 U39.8
TD_C_P: D2.1 D2.8 T21.3 U39.7
TD_D_N: D2.4 D2.5 T21.9 U39.11
TD_D_P: D2.3 D2.6 T21.8 U39.10
TRK1_1: U37.32
TRK1_2: U38.32
TRK2_1: U37.9
TRK2_2: U38.9
TTC_0: R810.1
TTC_3: R804.1
uart0_RxD: R779.1 U57.13
uart0_TxD: R778.1 U57.14
uart1_RxD: U1.AH13 U79.14
  other v2: 189.397,300.539
uart1_TxD: U1.AK13 U79.13
  other v2: 191.397,300.539
US+_DxN: R279.1 R286.1 U1.V15
  other v2: 179.397,302.539
US+_DxP: R282.1 R283.1 U1.V14
  other v2: 179.397,301.539
US+_GND_PS_ADC: C627.1 C628.1 FB39.2 U1.W21
  other v2: 180.397,308.539
US+_GNDADC: C629.1 C630.1 FB41.2 U1.R14 U1.U14 U1.U15
  other v2: 176.397,301.539 178.397,301.539 178.397,302.539
US+_MGTRref: R173.1 U1.K7
US+_MGTRref_K8: R695.2 U1.K8
  other v2: 171.397,295.539
US+_POR_OVE: R693.1 U1.Y6
  other v2: 181.397,293.539
US+_Pudc_B: R694.2 R696.1 U1.W7
  other v2: 180.397,294.539
US+_Vcc_PS_ADC: C627.2 C628.2 FB38.2 U1.W22 | length 1.8
  L1 w0.254: v1(198.768,309.397) 198.819,309.448 FB38.2@200.559,309.448
  other v2: 180.397,309.539
US+_Vcc_PS_Batt: B1.1 C747.1 C748.2 R276.1 U1.U20
  other v2: 178.397,307.539
US+_Vcc_PS_DDR_504: C616.2 C617.2 C618.2 C619.2 C620.2 C621.2 C622.2 C753.1 C754.2 C755.2 L18.2 R220.2 U1.AA24 U1.AB27 U1.AC25 U1.AD28 U1.AE26 U1.AG27 U1.AK26 | length 6.7
  L1 w0.116: v6(182.909,315.027) U1.AB27@183.397,314.539 ; v6(183.91,312.052) U1.AC25@184.397,312.539 ; v6(184.91,315.052) U1.AD28@185.397,315.539 ; U1.AE26@186.397,313.539 v6(186.884,314.027) ; v6(187.909,315.027) U1.AG27@188.397,314.539 ; U1.AK26@191.397,313.539 v6(191.884,314.027)
  L3 (Sign) w0.254: v6(182.909,315.027) v18@182.909,315.531 ; v6(183.91,312.052) v18@184.266,312.408 ; v6(184.91,315.052) v18@184.91,315.556 ; v18(187.897,315.544) 187.909,315.531 v6(187.909,315.027) ; v6(191.884,314.027) v18@192.241,313.671
  other v18: 184.266,312.427 192.259,313.67 182.897,315.544 184.897,315.569
US+_Vcc_PS_DDR_PLL: C631.2 C632.2 FB42.2 U1.U18 U1.U19
  other v2: 178.397,305.539 178.397,306.539
US+_Vcc_PS_IntFp: C738.1 C739.1 C740.2 C744.2 C745.2 C751.1 C752.2 C762.1 C763.2 R271.2 R617.2 U1.AA18 U1.AA20 U1.AA21 U1.AA22 U1.L11 U1.L13 U1.L17 U1.M12 U1.M14 U1.M16 U1.M18 U1.N11 U1.N13 U1.N15 U1.N17 U1.P12 U1.P14 U1.P16 U1.R10 U1.R11 U1.R13 U1.R17 U1.T9 U1.T10 U1.T12 U1.T16 U1.U8 U1.U9 U1.U10 U1.U11 U1.U13 U1.U17 U1.V8 U1.V10 U1.V12 U1.V16 U1.V17 U1.V18 U1.V19 U1.W11 U1.W13 U1.W15 U1.W17 U1.W19 U1.W20 U1.Y12 U1.Y14 U1.Y16 U1.Y17 U1.Y18 U1.Y19 U1.Y20 U1.Y22 U72.8 U72.9
  other v2: 178.397,295.539 179.397,295.539 177.397,296.539 178.397,296.539 176.397,297.539 177.397,297.539 178.397,297.539 179.397,297.539 172.397,298.539 174.397,298.539 176.397,298.539 178.397,298.539 180.397,298.539 173.397,299.539 175.397,299.539 177.397,299.539 179.397,299.539 181.397,299.539 172.397,300.539 174.397,300.539 176.397,300.539 178.397,300.539 180.397,300.539 173.397,301.539 175.397,301.539 181.397,301.539 174.397,302.539 180.397,302.539 173.397,303.539 175.397,303.539 177.397,303.539 179.397,303.539 181.397,303.539 172.397,304.539 174.397,304.539 176.397,304.539 178.397,304.539 179.397,304.539 180.397,304.539 181.397,304.539 173.397,305.539 179.397,305.539 181.397,305.539 182.397,305.539 179.397,306.539 180.397,306.539 181.397,306.539 180.397,307.539 181.397,307.539 182.397,307.539 182.397,308.539 181.397,309.539 182.397,309.539
  other v8: 142.777,289.801 144.53,289.801 146.282,289.801 139.272,289.801 141.025,289.801 139.272,291.554 141.025,291.554 142.777,291.554 144.53,291.554 146.282,291.554 142.777,293.306 144.53,293.306 146.282,293.306 139.272,293.306 141.025,293.306 139.272,295.059 141.025,295.059 142.777,295.059 144.53,295.059 146.282,295.059 142.777,296.812 144.53,296.812 146.282,296.812 139.272,296.812 141.025,296.812 139.272,298.564 141.025,298.564 142.777,298.564 144.53,298.564 146.282,298.564 142.777,300.317 144.53,300.317 146.282,300.317 139.272,300.317 141.025,300.317 139.272,302.07 141.025,302.07 142.777,302.069 144.53,302.069 146.282,302.069
US+_Vcc_PS_IntFpDDR: C764.1 C765.2
US+_VccADC: C629.2 C630.2 FB40.2 U1.R15
  other v2: 176.397,302.539
US+_VN: J29.1 U1.T15
  other v2: 177.397,302.539
US+_VP: J29.2 U1.T14
  other v2: 177.397,301.539
US_JTAG_CLK: U53.12
US_JTAG_TDI: U53.14
US_JTAG_TDO: U53.11
US_JTAG_TMS: U53.13
US_JTAG_Vcc: U53.15
US_PADI: C535.2 R374.1 U1.M21 X5.1 | length 3.5
  L1 w0.2: X5.1@147.843,332.125 X5.1@147.823,332.105 C535.2@147.823,330.314 147.823,329.597 148.198,329.222 R374.1@148.623,329.222
  other v2: 173.397,308.539
US_PADO: C536.2 R374.2 U1.N21 X5.2 | length 3.5
  L1 w0.2: R374.2@149.523,329.222 149.948,329.222 150.323,329.597 C536.2@150.323,330.314 X5.2@150.323,332.105
  other v2: 174.397,308.539
US_PS_DONE: R357.1 U1.N22 U43.6
  other v2: 174.397,309.539
US_PS_Err_Out: U1.R22 U43.3
  other v2: 176.397,309.539
US_PS_Err_Status: U1.R20 U43.4
  other v2: 176.397,307.539
US_PS_Init_B: R353.2 U1.N18 U43.5
  other v2: 174.397,305.539
US_PS_JTAG_TCK: R346.2 U1.L19
  other v2: 172.397,306.539
US_PS_JTAG_TDI: R347.2 U1.L20
  other v2: 172.397,307.539
US_PS_JTAG_TDO: U1.M20
  other v2: 173.397,307.539
US_PS_JTAG_TMS: R348.2 U1.L21
  other v2: 172.397,308.539
US_PS_Mode0: P2.4 R349.1 S1.1 U1.R18
  other v2: 176.397,305.539
US_PS_Mode2: P2.2 R351.1 S1.3 U1.P21
  other v2: 175.397,308.539
US_PS_Mode3: P2.1 R352.1 S1.4 U1.P22
  other v2: 175.397,309.539
US_PS_Prog_B: R356.2 R367.1 S2.1 S2.2 U1.M19
  other v2: 173.397,306.539
US_PS_Ref_Clk: R375.2 U1.P19
  other v2: 175.397,306.539
USB2_CLK: R362.2 U45.1
USB2_D0: R116.2 U45.3
USB2_D1: R117.2 U45.4
USB2_D2: R115.2 U45.5
USB2_D3: R119.2 U45.6
USB2_D4: R120.2 U45.7
USB2_D5: R121.2 U45.9
USB2_D6: R122.2 U45.10
USB2_D7: R802.1 U45.13
USB2_DIR: R800.1 U45.31
USB2_NXT: R801.1 U45.2
USB2_STP: R118.2 U45.29
USB_D_N: C537.2 D13.2 U45.19
USB_D_P: C537.3 D13.1 U45.18
USB_En_Vout: U45.17 U46.A2
USB_OSC_IN: C736.2 R491.1 U45.26 X7.1
USB_OSC_Out: C737.2 R491.2 U45.25 X7.3
USB_RS0: R376.1 U45.8
USB_RS1: R377.1 U45.11
USB_RS2: R378.1 U45.14
USB_RX_C_N: C537.5 C543.2 D14.1 D14.10
USB_RX_C_P: C537.6 C542.2 D14.2 D14.9
USB_RX_N: C543.1
USB_RX_P: C542.1
USB_TX_C_N: C537.8 C541.2 D14.4 D14.7
USB_TX_C_P: C537.9 C540.2 D14.5 D14.6
USB_TX_N: C541.1
USB_TX_P: C540.1
USB_Vbus: R490.1 U45.22
USB_Vdd33: C731.2 U45.20
USB_Vout: C538.2 C539.2 C734.2 FB26.1 R490.2 U46.C2 U46.D1 U46.D2 U46.E1 U46.E2 U46.F1 U46.F2
uSD_CLK: R96.2 R97.1 U47.C1 | length 2.8
  L16 w0.098: U47.C1@135.527,335.404 136.416,335.404 136.924,334.896 R96.2@138.087,334.896
uSD_CMD: R95.2 U47.D2 | length 5.4
  L14 (Sign) w0.098: v21(135.127,335.004) 136.067,335.004 137.004,334.067 v21(137.004,332.204)
  L16 w0.098: v21(137.004,332.204) 137.436,331.772 R95.2@138.087,331.772
uSD_D0: R87.2 U47.D1 | length 3.8
  L16 w0.098: U47.D1@135.527,335.004 135.824,335.004 136.719,334.109 136.719,333.577 137.483,332.814 R87.2@138.087,332.814
uSD_D1: R88.2 U47.E1 | length 5.5
  L16 w0.098: U47.E1@135.527,334.604 136.391,333.741 136.391,331.48 137.14,330.731 R88.2@138.087,330.731
uSD_D2: R89.2 U47.A1 | length 4.1
  L16 w0.098: U47.A1@135.527,336.204 135.527,337.474 136.073,338.021 R89.2@138.087,338.021
uSD_D3: R90.2 U47.B1 | length 2.6
  L16 w0.098: U47.B1@135.527,335.804 135.788,335.804 135.921,335.938 R90.2@138.087,335.938
uSD_D4: R91.2 U47.B2 | length 3.5
  L14 (Sign) w0.098: v21(135.127,335.804) 135.127,335.944 v21(136.099,336.916)
  L16 w0.098: v21(136.099,336.916) 136.167,336.916 136.23,336.979 R91.2@138.087,336.979
V_KEY: C609.2 R647.2 R648.1 R653.1 T24.1 T26.1 T28.1
V_PoE+: C595.2 C596.2 D3.1 D4.1 D27.1 R149.2 R324.2 T34.5 U65.18 | length 20.3
  L1 w0.254: R149.2@34.773,204.343 34.798,204.318 U65.18@36.92,204.318
  L16 w0.5: v5(27.345,228.551) C595.2@28.639,228.551 ; v5(28.639,229.845) C595.2@28.639,228.551 ; v5(29.932,228.551) C595.2@28.639,228.551 ; v5(35.686,223.896) D4.1@36.98,223.896 ; v5(36.98,225.19) D4.1@36.98,223.896 ; v5(38.274,223.896) D4.1@36.98,223.896 ; v5(45.554,223.832) D3.1@46.848,223.832 ; v5(46.848,222.539) D3.1@46.848,223.832 ; v5(46.848,225.126) D3.1@46.848,223.832 ; v5(48.141,223.832) D3.1@46.848,223.832 ; v5(48.998,226.657) R324.2@50.292,226.657 v5(50.292,227.951) ; v5(52.54,227.889) C596.2@52.54,226.595 v5(53.834,226.595)
VBB: C344.1 R257.1 U33.3 U33.4
VC1~: D3.4 T21.13 | length 21.6
  L16 w1: T21.13@40.432,251.716 44.386,247.762 44.386,235.194 D3.4@46.848,232.732
VC2~: D3.3 T21.14 | length 22.4
  L16 w1: T21.14@40.432,240.536 40.432,239.625 34.468,233.66 34.468,231.356 36.767,229.057 39.738,229.057 41.748,231.066 D3.3@41.748,232.732
VC3~: D4.4 T21.15 | length 22.8
  L16 w1: D4.4@36.98,232.796 36.98,233.601 42.608,239.23 42.608,245.567 38.972,249.203 T21.15@38.972,251.716
VC4~: D4.3 T21.16 | length 11.9
  L16 w1: D4.3@31.88,232.796 31.88,235.613 36.803,240.536 T21.16@38.972,240.536
Vcc_Aux_PCIE_PCIE0: C1_PCIE0.2 C2_PCIE0.2 C3_PCIE0.2 FB1_PCIE0.1 J1_PCIE0.2 J1_PCIE0.4
Vcc_Aux_PCIE_PCIE1: C1_PCIE1.2 C2_PCIE1.2 C3_PCIE1.2 FB1_PCIE1.1 J1_PCIE1.2 J1_PCIE1.4
Vcc_Aux_PCIE_PCIE2: C1_PCIE2.2 C2_PCIE2.2 C3_PCIE2.2 FB1_PCIE2.1 J1_PCIE2.2 J1_PCIE2.4
Vcc_Aux_PCIE_PCIE3: C1_PCIE3.2 C2_PCIE3.2 C3_PCIE3.2 FB1_PCIE3.1 J1_PCIE3.2 J1_PCIE3.4
Vcc_Aux_PCIE_PCIE4: C1_PCIE4.2 C2_PCIE4.2 C3_PCIE4.2 FB1_PCIE4.1 J1_PCIE4.2 J1_PCIE4.4
Vcc_CLK_Mux_Fine: C326.2 C327.2 C328.2 C329.2 FB23.2 R250.1 R251.1 R259.1 R260.1 R386.1 R486.1 R488.2 U31.5 U32.5
Vcc_SFP_0: R155.2 R156.2 R157.2 R158.2 R161.2 R162.2
VCCINT: C598.2 D26.2 R669.1 U65.4 U65.14 | length 8.4
  L1 w0.254: C598.2@37.846,208.912 38.26,208.498 U65.14@38.26,206.158 ; R669.1@38.887,200.831 39.26,201.204 U65.4@39.26,202.478
  L1 w0.5: D26.2@34.353,208.547 36.347,208.547 36.713,208.912 C598.2@37.846,208.912
VCCO_1: C398.2 R289.2 R293.1 R295.1 R296.1 U37.2 U37.4 | length 1
  L1 w0.254: R293.1@60.881,178.317 R289.2@60.881,179.317
VCCO_2: C439.2 R307.2 R310.1 R313.1 R314.1 U38.2 U38.4 | length 6.6
  L1 w0.254: R307.2@58.845,206.596 59.525,206.596 59.643,206.714 U38.4@61.453,206.714 ; C439.2@58.845,209.529 R310.1@58.845,208.526 60.003,208.526 60.815,207.714 U38.2@61.453,207.714
VDD_APLL1: C88.1 C110.2 FB13.2 U16.49
VDD_APLL2: C89.1 C127.2 FB15.2 U16.37
VDD_CLK_MUX_DIV_3.3V: C336.2 C337.2 C338.2 C340.2 FB24.2 U33.1 U33.8 U33.9 U33.12
VDD_DIG: C93.1 C165.2 C590.2 FB21.2 FB37.1 R1.2 R125.1 R127.2 R128.2 R366.1 R544.2 U16.8
VDD_IN0: C63.1 C101.2 FB8.2 U16.3
VDD_IN1: C64.1 C105.2 FB10.2 U16.16
VDD_IN2: C67.1 C109.2 FB12.2 U16.9
VDD_IN3: C70.1 C126.2 FB14.2 U16.4
VDD_TCXO: C92.1 C148.2 FB19.2 U16.19
VDD_XO: C90.1 C144.2 FB17.2 U16.42
VDDO_0: C75.1 C143.2 FB16.2 U16.21
VDDO_1: C76.1 C147.2 FB18.2 U16.25
VDDO_6: C77.1 C164.2 FB20.2 U16.59
VDDO_7: C81.1 C180.2 FB22.2 U16.63
VDDO_23: C82.1 C102.2 FB9.2 U16.30
VDDO_45: C83.1 C106.2 FB11.2 U16.50
VLDO: C544.2 R383.2 U47.B4
Vout1_1: C406.2 C407.2 C408.2 C409.2 C410.2 C411.2 C412.2 C413.2 C414.2 C415.2 C416.2 C417.2 L11.2 R448_U_Pomiar_pradu_napiecia_3.1 U64_U_Pomiar_pradu_napiecia_3.10 | length 10.2
  L1 w0.3: R448_U_Pomiar_pradu_napiecia_3.1@107.759,180.301 107.759,181.902 108.017,182.159 U64_U_Pomiar_pradu_napiecia_3.10@116.278,182.159
Vout1_2: C447.2 C448.2 C449.2 C450.2 C451.2 C452.2 C453.2 C454.2 C455.2 C456.2 C457.2 C458.2 L19.2 R448_U_Pomiar_pradu_napiecia_5.1 U64_U_Pomiar_pradu_napiecia_5.10
Vout2_1: C418.2 C419.2 C420.2 C421.2 C422.2 C423.2 C424.2 C425.2 C426.2 C427.2 C428.2 C429.2 L12.2 R448_U_Pomiar_pradu_napiecia_4.1 U64_U_Pomiar_pradu_napiecia_4.10
Vout2_2: C459.2 C460.2 C461.2 C462.2 C463.2 C464.2 C465.2 C466.2 C467.2 C468.2 C469.2 C470.2
Vout_1_Selector: C4.1 C5.1 C6.1 C7.1 C8.2 C9.2 C10.2 C11.2 C20.2 C21.2 C22.2 C23.2 C24.2 C25.2 C26.2 C27.2 R15.2 U4.7 U5.1 U5.8 | length 39.1
  L1 w0.5: v1(37.904,169.788) C4.1@38.991,169.788 ; v1(37.904,170.893) C4.1@38.991,170.893 ; v1(37.904,171.99) C4.1@38.991,171.99 ; v1(37.904,173.243) C5.1@38.991,173.243 ; v1(37.904,174.348) C5.1@38.991,174.348 ; v1(37.904,175.445) C5.1@38.991,175.445 ; v1(37.904,176.697) C7.1@38.991,176.697 ; v1(37.904,177.802) C7.1@38.991,177.802 ; v1(37.904,178.899) C7.1@38.991,178.899 ; v1(37.904,180.152) C6.1@38.991,180.152 ; v1(37.904,181.257) C6.1@38.991,181.257 ; v1(37.904,182.353) C6.1@38.991,182.353 ; C4.1@38.991,170.337 v1(40.078,170.337) ; C4.1@38.991,171.442 v1(40.078,171.442) ; C5.1@38.991,173.791 v1(40.078,173.791) ; C5.1@38.991,174.896 v1(40.078,174.896) ; C7.1@38.991,177.246 v1(40.078,177.246) ; C7.1@38.991,178.351 v1(40.078,178.351) ; C6.1@38.991,180.7 v1(40.078,180.7) ; C6.1@38.991,181.805 v1(40.078,181.805) ; v1(53.932,163.773) C20.2@55.019,163.774 ; v1(53.932,164.497) C20.2@55.019,164.497 ; v1(53.959,166.505) C27.2@55.046,166.505 ; v1(53.959,168.403) C22.2@55.046,168.403 ; v1(53.959,170.301) C21.2@55.046,170.301 ; v1(53.959,172.199) C24.2@55.046,172.199 ; v1(53.959,174.096) C25.2@55.046,174.096 ; v1(53.959,175.994) C23.2@55.046,175.994 ; v1(53.959,165.781) C27.2@55.046,165.781 ; v1(53.959,167.679) C22.2@55.046,167.679 ; v1(53.959,169.577) C21.2@55.046,169.577 ; v1(53.959,171.475) C24.2@55.046,171.475 ; v1(53.959,173.373) C25.2@55.046,173.373 ; v1(53.959,175.27) C23.2@55.046,175.27 ; v1(53.989,177.168) C26.2@55.076,177.168 ; v1(53.989,177.892) C26.2@55.076,177.892
  other v5: 50.48,171.336 49.821,172.073 49.233,172.838 50.481,172.838 49.233,177.161 50.481,177.161 49.821,177.926 50.48,178.663 46.94,180.658 47.599,181.395 46.939,182.16 48.188,182.16
  other v10: 49.06,174.6 49.06,175.4 48.36,183.921
Vout_2_Selector: C12.1 C13.1 C14.1 C15.1 C16.2 C17.2 C18.2 C19.2 C28.2 C29.2 C30.2 C31.2 C32.2 C33.2 C34.2 C35.2 R677.2 R678.2 U4.1 U4.8 U48.7 | length 40.8
  L1 w0.5: v1(37.823,183.811) C12.1@38.91,183.811 ; v1(37.823,184.916) C12.1@38.91,184.916 ; v1(37.823,186.012) C12.1@38.91,186.012 ; v1(37.823,187.256) C15.1@38.91,187.256 ; v1(37.823,188.361) C15.1@38.91,188.361 ; v1(37.823,189.458) C15.1@38.91,189.457 ; v1(37.823,190.701) C13.1@38.91,190.701 ; v1(37.823,191.806) C13.1@38.91,191.806 ; v1(37.823,192.903) C13.1@38.91,192.903 ; v1(37.823,194.146) C14.1@38.91,194.146 ; v1(37.823,195.251) C14.1@38.91,195.251 ; v1(37.823,196.348) C14.1@38.91,196.348 ; C12.1@38.91,184.359 v1(39.997,184.359) ; C12.1@38.91,185.464 v1(39.997,185.464) ; C15.1@38.91,187.804 v1(39.997,187.804) ; C15.1@38.91,188.909 v1(39.997,188.909) ; C13.1@38.91,191.249 v1(39.997,191.249) ; C13.1@38.91,192.354 v1(39.997,192.354) ; C14.1@38.91,194.694 v1(39.997,194.694) ; C14.1@38.91,195.799 v1(39.997,195.799) ; v5(43.658,191.22) R678.2@43.658,192.033 ; v5(44.716,191.22) R677.2@44.716,192.033 ; v1(53.971,179.205) C31.2@55.058,179.205 ; v1(53.971,179.929) C31.2@55.058,179.929 ; v1(53.971,181.103) C30.2@55.058,181.103 ; v1(53.971,181.827) C30.2@55.058,181.827 ; v1(53.971,183.001) C32.2@55.058,183.001 ; v1(53.971,183.725) C32.2@55.058,183.725 ; v1(53.971,184.899) C29.2@55.058,184.899 ; v1(53.971,185.623) C29.2@55.058,185.623 ; v1(53.971,186.796) C28.2@55.058,186.796 ; v1(53.971,187.52) C28.2@55.058,187.52 ; v1(53.971,188.694) C33.2@55.058,188.694 ; v1(53.971,189.418) C33.2@55.058,189.418 ; v1(53.971,190.592) C34.2@55.058,190.592 ; v1(53.971,191.316) C34.2@55.058,191.316 ; v1(53.997,192.534) C35.2@55.084,192.534 ; v1(53.996,193.258) C35.2@55.083,193.258
  other v5: 50.48,180.658 49.821,181.395 49.233,182.16 50.481,182.16 49.233,186.483 50.481,186.483 49.821,187.248 50.48,187.985 46.907,190.32 47.566,191.057 46.906,191.822 48.155,191.821
  other v10: 49.06,183.921 49.06,184.721 48.327,193.583
Vout_5V@10A_INA: L20.2 R448_U_Pomiar_pradu_napiecia_6.1 U64_U_Pomiar_pradu_napiecia_6.10
VPHY_FTDI: C661.2 C662.2 FB44.2 U55.4
VPLL_FTDI: C659.2 C660.2 FB43.2 U55.9
VREF+_1: C61.2 C62.2 FB3.2 U12.44
VREF+_2: C73.2 C74.2 FB5.2 U13.44
VREF+_3: C57.2 C58.2 FB2.2 U14.44
VVCO+_1: C86.2 C87.2 FB6.2 U12.39
VVCO+_2: C97.2 C98.2 FB7.2 U13.39
VVCO+_3: C68.2 C69.2 FB4.2 U14.39
WR_LMK_CLK_HF1_N: U1.AK5 U16.26
WR_LMK_CLK_HF1_P: U1.AJ5 U16.27
WR_LMK_CLK_HF2_N: U1.AK2 U16.32
  other v2: 191.397,289.539
WR_LMK_CLK_HF2_P: U1.AK3 U16.31
WR_LMK_CLK_HF3_N: U16.33
WR_LMK_CLK_HF3_P: U16.34
WR_LMK_CLK_HF4_N: U16.52
WR_LMK_CLK_HF4_P: U16.51
WR_LMK_CLK_HF5_N: U16.53
WR_LMK_CLK_HF5_P: U16.54
WR_LMK_CLK_HF6_N: U16.58
WR_LMK_CLK_HF6_P: U16.57
WR_LMK_CLK_HF7_N: U16.61
WR_LMK_CLK_HF7_P: U16.62
WR_LMK_CLK_IN_N: C594.2 R311.1 U16.2
WR_LMK_CLK_IN_P: C593.2 R311.2 U16.1
WR_LMK_CLK_LF_N: U16.15 U16.23
WR_LMK_CLK_LF_P: U16.14 U16.22
WR_Source_CLK_N: C594.1 U13.6
WR_Source_CLK_P: C593.1 U13.7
